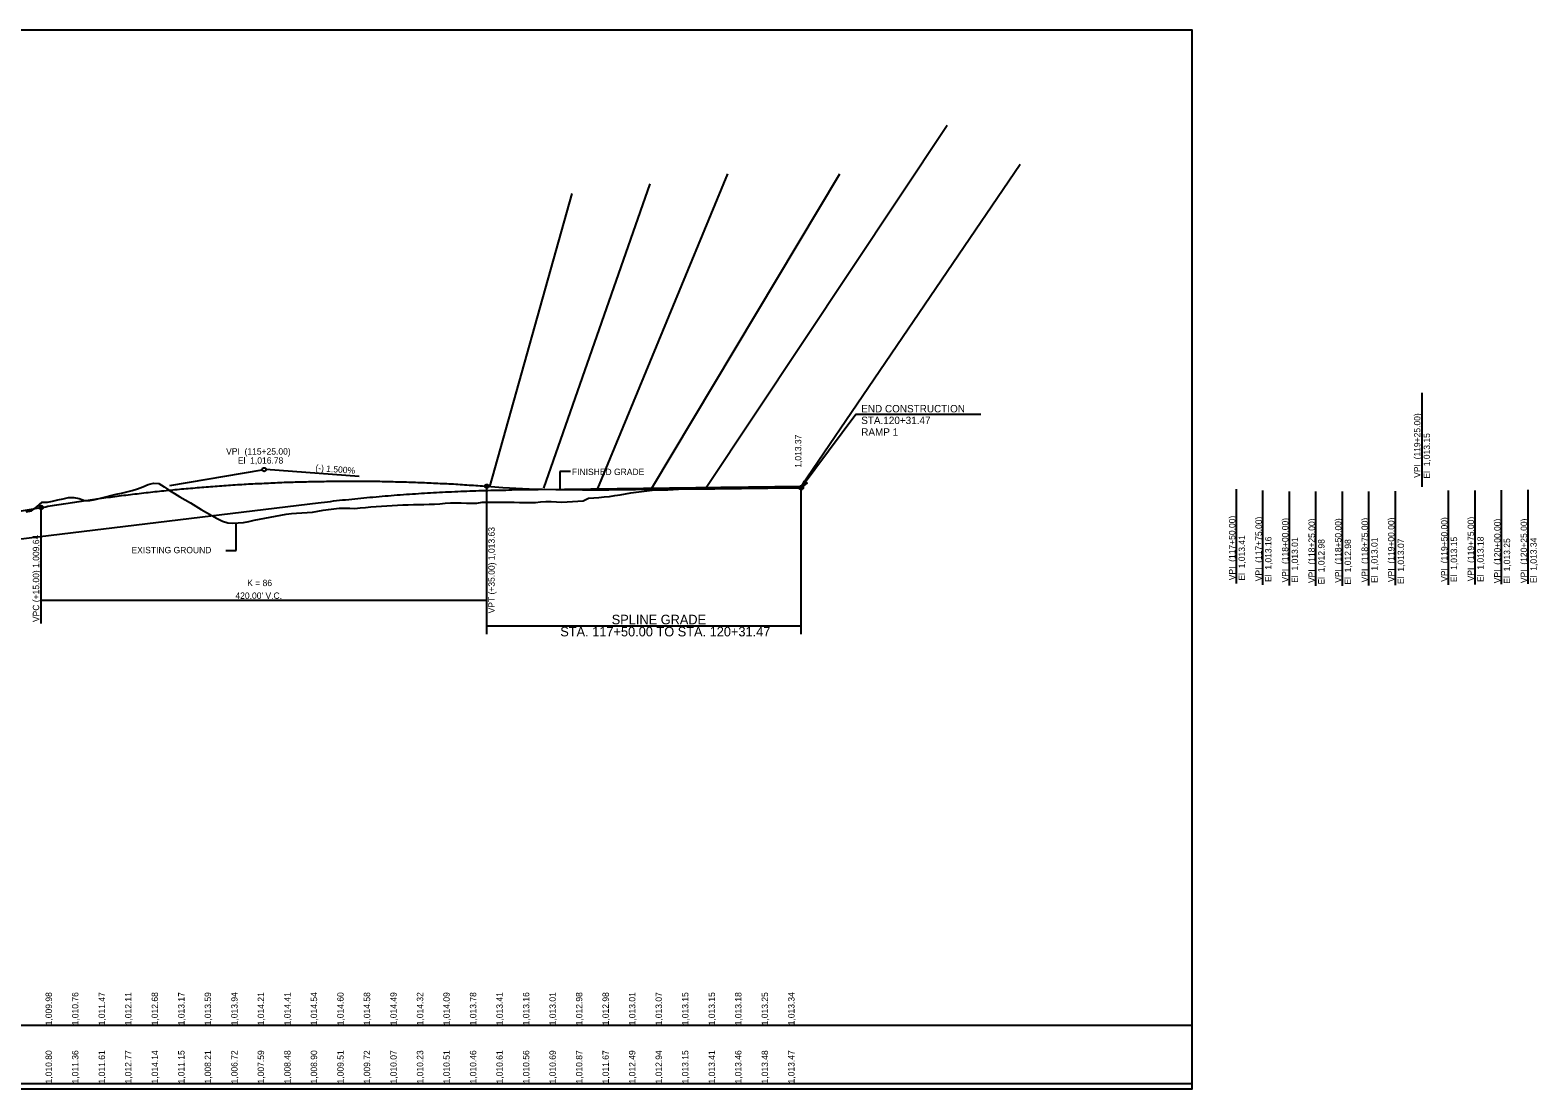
# Model space of a CAD drawing. Extents: x 16972094 to 16980746, y 12563782 to 12565536.
# Drawn here: x 16979324 to 16980746, y 12564538 to 12565536 of the extents above; entities that cross this region are included whole.
import ezdxf

# ---------------------------------------------------------------- set-up
doc = ezdxf.new("R2010")
doc.units = 0
for name, color, linetype in [('Default', 7, 'Continuous'), ('RD_DDB_EX_Tx', 7, 'Continuous'), ('RD_DDB_PR_Tx', 7, 'Continuous'), ('RD_DTM_BkLn1', 7, 'Continuous'), ('RD_EX_BldgChurch', 7, 'Continuous'), ('RD_EX_H2O_Ditch Bottom', 7, 'Continuous'), ('RD_HC_Data', 7, 'Continuous'), ('RD_HY_Area_Dtch', 7, 'Continuous'), ('RD_PD_Supershp_I385', 7, 'Continuous'), ('RD_PD_Supershp_Ramp_7', 7, 'Continuous'), ('RD_SHT_Typical', 7, 'Continuous'), ('RD_Sketch2', 7, 'Continuous'), ('RD_Sketch3', 7, 'Continuous'), ('RD_TX_RoadID', 7, 'Continuous'), ('S_HydraCrossSection', 7, 'Continuous')]:
    doc.layers.add(name, color=color, linetype=linetype)

msp = doc.modelspace()

# ---------------------------------------------------------------- linework, layer by layer
at = {"layer": 'Default'}
msp.add_lwpolyline([(16978919.9, 12564537.8), (16980419.9, 12564537.8), (16980419.9, 12565536), (16978919.9, 12565536)], close=True, dxfattribs=at)
at = {"layer": 'RD_DDB_EX_Tx'}
for p, q in [((16979518.5, 12565045.3), (16979518.5, 12565071.4)), ((16979508.8, 12565045.3), (16979518.5, 12565045.3))]:
    msp.add_line(p, q, dxfattribs=at)
at = {"layer": 'RD_DDB_PR_Tx'}
for p, q in [((16979823.7, 12565119.8), (16979823.7, 12565102.3)), ((16979833.6, 12565119.8), (16979823.7, 12565119.8))]:
    msp.add_line(p, q, dxfattribs=at)
at = {"layer": 'RD_DTM_BkLn1'}
for p, q in [((16978919.9, 12564597.8), (16980419.9, 12564597.8)), ((16978919.9, 12564542.8), (16980419.9, 12564542.8))]:
    msp.add_line(p, q, dxfattribs=at)
at = {"layer": 'RD_EX_BldgChurch'}
for points in [[(16979320.6, 12565081.9), (16979325.6, 12565082.8), (16979330.6, 12565086.4), (16979335.6, 12565090.9), (16979340.6, 12565090.9), (16979345.6, 12565091.9), (16979350.6, 12565093), (16979355.6, 12565094.2), (16979360.6, 12565095.3), (16979365.6, 12565095.5), (16979370.6, 12565094.5), (16979375.6, 12565092.6), (16979380.6, 12565092.6), (16979385.6, 12565093.4), (16979390.6, 12565094.7), (16979395.6, 12565096), (16979400.6, 12565097.2), (16979405.6, 12565098.4), (16979410.6, 12565099.5), (16979415.6, 12565100.6), (16979420.6, 12565101.8), (16979425.6, 12565103.5), (16979430.6, 12565105.5), (16979435.6, 12565107.5), (16979440.6, 12565108.8), (16979445.6, 12565108.4), (16979450.6, 12565105.3), (16979455.6, 12565102.1), (16979460.6, 12565099), (16979465.6, 12565096), (16979470.6, 12565093.2), (16979475.6, 12565090.3), (16979480.6, 12565087.2), (16979485.6, 12565083.9)], [(16979485.6, 12565083.9), (16979490.6, 12565081.2), (16979495.6, 12565078.5), (16979500.6, 12565075.7), (16979505.6, 12565073.1), (16979510.6, 12565071.5), (16979515.6, 12565071.3), (16979520.6, 12565071.4), (16979525.6, 12565071.8), (16979530.6, 12565072.8), (16979535.6, 12565073.9), (16979540.6, 12565074.9), (16979545.6, 12565075.9), (16979550.6, 12565076.9), (16979555.6, 12565077.8), (16979560.6, 12565078.7), (16979565.6, 12565079.7), (16979570.6, 12565080.3), (16979575.6, 12565080.6), (16979580.6, 12565080.9), (16979585.6, 12565081.3), (16979590.6, 12565081.6), (16979595.6, 12565082.4), (16979600.6, 12565083.3), (16979605.6, 12565084.1), (16979610.6, 12565084.6), (16979615.6, 12565085.2), (16979620.6, 12565085.4), (16979625.6, 12565085.2), (16979630.6, 12565085), (16979635.6, 12565085.5), (16979640.6, 12565086), (16979645.6, 12565086.5), (16979650.6, 12565087), (16979655.6, 12565087.3), (16979660.6, 12565087.6), (16979665.6, 12565087.9), (16979670.6, 12565088.2), (16979675.6, 12565088.4), (16979680.6, 12565088.5), (16979685.6, 12565088.7), (16979690.6, 12565088.8), (16979695.6, 12565088.9), (16979700.6, 12565089), (16979705.6, 12565089), (16979710.6, 12565089.4), (16979715.6, 12565090), (16979720.6, 12565090.4), (16979725.6, 12565090.3), (16979730.6, 12565090.2), (16979735.6, 12565090.1), (16979740.6, 12565090), (16979745.6, 12565090.1), (16979750.6, 12565090.8), (16979755.6, 12565091.1), (16979760.6, 12565091), (16979765.6, 12565090.9), (16979770.6, 12565090.9), (16979775.6, 12565090.9), (16979780.6, 12565090.8), (16979785.6, 12565090.7), (16979790.6, 12565090.5), (16979795.6, 12565090.6), (16979800.6, 12565090.7), (16979805.6, 12565091.3), (16979810.6, 12565091.7), (16979815.6, 12565091.5), (16979820.6, 12565091.2), (16979825.6, 12565090.8), (16979830.6, 12565091.3), (16979835.6, 12565091.6), (16979840.6, 12565091.9), (16979845.6, 12565092.2), (16979850.6, 12565094.6), (16979855.6, 12565095), (16979860.6, 12565095.3), (16979865.6, 12565095.9), (16979870.6, 12565096.2), (16979875.6, 12565097.1), (16979880.6, 12565098), (16979885.6, 12565098.9), (16979890.6, 12565099.6), (16979895.6, 12565100.4), (16979900.6, 12565100.9), (16979905.6, 12565101.7), (16979910.6, 12565102.2), (16979915.6, 12565102.5), (16979920.6, 12565102.5), (16979925.6, 12565102.6), (16979930.6, 12565103), (16979935.6, 12565103.3), (16979940.6, 12565103.5), (16979945.6, 12565103.5), (16979950.6, 12565103.7), (16979955.6, 12565104.2), (16979960.6, 12565104.1), (16979965.6, 12565104.6), (16979970.6, 12565104.9), (16979975.6, 12565105), (16979980.6, 12565105.1), (16979985.6, 12565105.1)], [(16979985.6, 12565105.1), (16979990.6, 12565105.1), (16979995.6, 12565105.1), (16980000.6, 12565105.1), (16980005.6, 12565105.1), (16980010.6, 12565105.2), (16980015.6, 12565105.2), (16980020.6, 12565105.2), (16980025.6, 12565105.1), (16980030.6, 12565105.1), (16980035.6, 12565105.2), (16980040.6, 12565105.2), (16980045.6, 12565105.1), (16980050.6, 12565105.2), (16980051.3, 12565105.2)]]:
    msp.add_lwpolyline(points, dxfattribs=at)
at = {"layer": 'RD_EX_H2O_Ditch Bottom'}
for p, q in [((16979456.1, 12565106.6), (16979543.1, 12565121.4)), ((16979634.6, 12565115), (16979546.6, 12565121.6))]:
    msp.add_line(p, q, dxfattribs=at)
for centre in [(16979544.9, 12565121.7), (16980051.3, 12565104.6)]:
    msp.add_circle(centre, 1.75, dxfattribs=at)
at = {"layer": 'RD_HC_Data'}
msp.add_line((16979754.9, 12564974.4), (16980051.3, 12564974.4), dxfattribs=at)
at = {"layer": 'RD_HY_Area_Dtch'}
for p, q in [((16979961.5, 12565104.8), (16980188.7, 12565446.3)), ((16980051.3, 12565105.9), (16980257.5, 12565409.6)), ((16979859.4, 12565103.9), (16979982.1, 12565400.4)), ((16979910.4, 12565104.2), (16980087.7, 12565400.4)), ((16979757.6, 12565105.3), (16979835.2, 12565382)), ((16979808.5, 12565104.3), (16979908.7, 12565391.2))]:
    msp.add_line(p, q, dxfattribs=at)
at = {"layer": 'RD_SHT_Typical'}
msp.add_line((16980220.4, 12565173.6), (16980103.8, 12565173.6), dxfattribs=at)
msp.add_lwpolyline([(16980103.8, 12565173.6), (16980102.7, 12565173.6), (16980051.3, 12565104.6)], dxfattribs=at)
msp.add_lwpolyline([(16980053.9, 12565111.1), (16980051.3, 12565104.6), (16980056.8, 12565109)], close=True, dxfattribs=at)
at = {"layer": 'RD_Sketch2'}
for p, q in [((16980636.4, 12565105.3), (16980636.4, 12565194)), ((16979754.9, 12564966.6), (16979754.9, 12565104.2)), ((16980051.3, 12564966.6), (16980051.3, 12565102.9)), ((16980461.4, 12565014.4), (16980461.4, 12565103.1)), ((16980486.4, 12565013.1), (16980486.4, 12565101.8)), ((16980511.4, 12565012.4), (16980511.4, 12565101.1)), ((16980536.4, 12565012.2), (16980536.4, 12565100.9)), ((16980561.4, 12565012.2), (16980561.4, 12565100.9)), ((16980586.4, 12565012.4), (16980586.4, 12565101.1)), ((16980611.4, 12565012.7), (16980611.4, 12565101.4)), ((16980661.4, 12565013.1), (16980661.4, 12565101.8)), ((16980686.4, 12565013.2), (16980686.4, 12565102)), ((16980711.4, 12565013.5), (16980711.4, 12565102.3)), ((16980736.4, 12565014), (16980736.4, 12565102.7)), ((16979334.9, 12564976.7), (16979334.9, 12565084.3)), ((16979334.9, 12564998.5), (16979754.9, 12564998.5))]:
    msp.add_line(p, q, dxfattribs=at)
for centre in [(16979754.9, 12565106), (16979334.9, 12565086)]:
    msp.add_circle(centre, 1.75, dxfattribs=at)
at = {"layer": 'RD_Sketch3'}
for p, q in [((16979778.5, 12565102.5), (16980051.3, 12565105.9)), ((16978882, 12565004.1), (16979596, 12565090.4))]:
    msp.add_line(p, q, dxfattribs=at)
msp.add_open_spline([(16979596, 12565090.4), (16979687.3, 12565101.4), (16979778.5, 12565102.5)], degree=2, dxfattribs=at)
at = {"layer": 'RD_TX_RoadID'}
for p, q in [((16979754.9, 12565106), (16979769.9, 12565104.8)), ((16979769.9, 12565104.8), (16979794.9, 12565103.6)), ((16979794.9, 12565103.6), (16979819.9, 12565102.9)), ((16979819.9, 12565102.9), (16979844.9, 12565102.7)), ((16979844.9, 12565102.7), (16979869.9, 12565102.7)), ((16979869.9, 12565102.7), (16979894.9, 12565102.8)), ((16979894.9, 12565102.8), (16979919.9, 12565103.1)), ((16979919.9, 12565103.1), (16979944.9, 12565103.5)), ((16979944.9, 12565103.5), (16979969.9, 12565103.5)), ((16979969.9, 12565103.5), (16979994.9, 12565103.7)), ((16979994.9, 12565103.7), (16980019.9, 12565104)), ((16980019.9, 12565104), (16980044.9, 12565104.5)), ((16980044.9, 12565104.5), (16980051.3, 12565104.6)), ((16978919.9, 12565015.5), (16979334.9, 12565086))]:
    msp.add_line(p, q, dxfattribs=at)
msp.add_spline([(16979334.9, 12565086), (16979343.3, 12565087.4), (16979351.7, 12565088.8), (16979360.1, 12565090.1), (16979368.5, 12565091.4), (16979376.9, 12565092.6), (16979385.3, 12565093.8), (16979393.7, 12565095), (16979402.1, 12565096.1), (16979410.5, 12565097.2), (16979418.9, 12565098.2), (16979427.3, 12565099.2), (16979435.7, 12565100.2), (16979444.1, 12565101.1), (16979452.5, 12565102), (16979460.9, 12565102.8), (16979469.3, 12565103.6), (16979477.7, 12565104.3), (16979486.1, 12565105), (16979494.5, 12565105.7), (16979502.9, 12565106.3), (16979511.3, 12565106.9), (16979519.7, 12565107.5), (16979528.1, 12565108), (16979536.5, 12565108.4), (16979544.9, 12565108.8), (16979553.3, 12565109.2), (16979561.7, 12565109.6), (16979570.1, 12565109.9), (16979578.5, 12565110.1), (16979586.9, 12565110.3), (16979595.3, 12565110.5), (16979603.7, 12565110.6), (16979612.1, 12565110.7), (16979620.5, 12565110.8), (16979628.9, 12565110.8), (16979637.3, 12565110.7), (16979645.7, 12565110.7), (16979654.1, 12565110.6), (16979662.5, 12565110.4), (16979670.9, 12565110.2), (16979679.3, 12565110), (16979687.7, 12565109.7), (16979696.1, 12565109.4), (16979704.5, 12565109), (16979712.9, 12565108.6), (16979721.3, 12565108.2), (16979729.7, 12565107.7), (16979738.1, 12565107.1), (16979746.5, 12565106.6), (16979754.9, 12565106)], degree=3, dxfattribs=at)

# ---------------------------------------------------------------- texts
at = {"layer": 'RD_DDB_EX_Tx'}
msp.add_text('EXISTING GROUND', height=6, dxfattribs=at).set_placement((16979419.9, 12565042.8))
at = {"layer": 'RD_DDB_PR_Tx'}
msp.add_text('FINISHED GRADE', height=6, dxfattribs=at).set_placement((16979835.1, 12565116.5))
at = {"layer": 'RD_EX_H2O_Ditch Bottom'}
for s, p in [('VPI  (119+25.00)', (16980634.9, 12565113.9)), ('1,013.37', (16980051.3, 12565123.4)), ('El  1,013.15', (16980643.9, 12565113.2)), ('VPI  (117+50.00)', (16980460.4, 12565017.3)), ('VPI  (117+75.00)', (16980485.4, 12565016.4)), ('VPI  (118+00.00)', (16980510.4, 12565015.2)), ('VPI  (118+25.00)', (16980535.4, 12565014.7)), ('VPI  (118+50.00)', (16980560.4, 12565014.9)), ('VPI  (118+75.00)', (16980585.4, 12565015.3)), ('VPI  (119+00.00)', (16980610.4, 12565015.6)), ('VPI  (119+50.00)', (16980660.4, 12565015.9)), ('VPI  (119+75.00)', (16980685.4, 12565016.3)), ('VPI  (120+00.00)', (16980710.4, 12565014.5)), ('VPI  (120+25.00)', (16980735.4, 12565014.6)), ('El  1,013.41', (16980469.5, 12565017)), ('El  1,013.16', (16980494.5, 12565015.7)), ('El  1,013.01', (16980519.5, 12565014.9)), ('El  1,012.98', (16980544.5, 12565013.3)), ('El  1,012.98', (16980569.5, 12565013.2)), ('El  1,013.01', (16980594.5, 12565014.8)), ('El  1,013.07', (16980619.5, 12565013.8)), ('El  1,013.15', (16980669.5, 12565015.5)), ('El  1,013.18', (16980694.5, 12565015.7)), ('El  1,013.25', (16980719.5, 12565014.1)), ('El  1,013.34', (16980744.5, 12565014.7))]:
    msp.add_text(s, height=6, rotation=90, dxfattribs=at).set_placement(p)
for s, p in [('VPI  (115+25.00)', (16979509.1, 12565135.8)), ('El  1,016.78', (16979520.2, 12565127.3))]:
    msp.add_text(s, height=6, dxfattribs=at).set_placement(p)
at = {"layer": 'RD_HC_Data'}
for s, p in [('SPLINE GRADE', (16979872.6, 12564975.8)), ('STA. 117+50.00 TO STA. 120+31.47', (16979824.1, 12564964.4))]:
    msp.add_text(s, height=9, dxfattribs=at).set_placement(p)
at = {"layer": 'RD_PD_Supershp_I385'}
for s, p in [('1,009.98', (16979344.9, 12564597.7)), ('1,010.76', (16979369.9, 12564597.7)), ('1,011.47', (16979394.9, 12564597.7)), ('1,012.11', (16979419.9, 12564597.7)), ('1,012.68', (16979444.9, 12564597.7)), ('1,013.17', (16979469.9, 12564597.7)), ('1,013.59', (16979494.9, 12564597.7)), ('1,013.94', (16979519.9, 12564597.7)), ('1,014.21', (16979544.9, 12564597.7)), ('1,014.41', (16979569.9, 12564597.7)), ('1,014.54', (16979594.9, 12564597.7)), ('1,014.60', (16979619.9, 12564597.7)), ('1,014.58', (16979644.9, 12564597.7)), ('1,014.49', (16979669.9, 12564597.7)), ('1,014.32', (16979694.9, 12564597.7)), ('1,014.09', (16979719.9, 12564597.7)), ('1,013.78', (16979744.9, 12564597.7)), ('1,013.41', (16979769.9, 12564597.7)), ('1,013.16', (16979794.9, 12564597.7)), ('1,013.01', (16979819.9, 12564597.7)), ('1,012.98', (16979844.9, 12564597.7)), ('1,012.98', (16979869.9, 12564597.7)), ('1,013.01', (16979894.9, 12564597.7)), ('1,013.07', (16979919.9, 12564597.7)), ('1,013.15', (16979944.9, 12564597.7)), ('1,013.15', (16979969.9, 12564597.7)), ('1,013.18', (16979994.9, 12564597.7)), ('1,013.25', (16980019.9, 12564597.7)), ('1,013.34', (16980044.9, 12564597.7))]:
    msp.add_text(s, height=6, rotation=90, dxfattribs=at).set_placement(p)
at = {"layer": 'RD_PD_Supershp_Ramp_7'}
for s, p in [('1,010.80', (16979344.9, 12564542.9)), ('1,011.36', (16979369.9, 12564542.9)), ('1,011.61', (16979394.9, 12564542.9)), ('1,012.77', (16979419.9, 12564542.9)), ('1,014.14', (16979444.9, 12564542.9)), ('1,011.15', (16979469.9, 12564542.9)), ('1,008.21', (16979494.9, 12564542.9)), ('1,006.72', (16979519.9, 12564542.9)), ('1,007.59', (16979544.9, 12564542.9)), ('1,008.48', (16979569.9, 12564542.9)), ('1,008.90', (16979594.9, 12564542.9)), ('1,009.51', (16979619.9, 12564542.9)), ('1,009.72', (16979644.9, 12564542.9)), ('1,010.07', (16979669.9, 12564542.9)), ('1,010.23', (16979694.9, 12564542.9)), ('1,010.51', (16979719.9, 12564542.9)), ('1,010.46', (16979744.9, 12564542.9)), ('1,010.61', (16979769.9, 12564542.9)), ('1,010.56', (16979794.9, 12564542.9)), ('1,010.69', (16979819.9, 12564542.9)), ('1,010.87', (16979844.9, 12564542.9)), ('1,011.67', (16979869.9, 12564542.9)), ('1,012.49', (16979894.9, 12564542.9)), ('1,012.94', (16979919.9, 12564542.9)), ('1,013.15', (16979944.9, 12564542.9)), ('1,013.41', (16979969.9, 12564542.9)), ('1,013.46', (16979994.9, 12564542.9)), ('1,013.48', (16980019.9, 12564542.9)), ('1,013.47', (16980044.9, 12564542.9))]:
    msp.add_text(s, height=6, rotation=90, dxfattribs=at).set_placement(p)
at = {"layer": 'RD_SHT_Typical'}
for s, p in [('END CONSTRUCTION', (16980107.8, 12565175.6)), ('STA.120+31.47 ', (16980107.8, 12565164.6)), ('RAMP 1', (16980107.8, 12565153.6))]:
    msp.add_text(s, height=7, dxfattribs=at).set_placement(p)
at = {"layer": 'RD_Sketch2'}
for s, p in [('VPT (+35.00) 1,013.63', (16979762.3, 12564986.1)), ('VPC (+15.00) 1,009.64', (16979332.9, 12564977.9))]:
    msp.add_text(s, height=6, rotation=90, dxfattribs=at).set_placement(p)
for s, p in [('K = 86', (16979529, 12565011.8)), ("420.00' V.C.", (16979517.9, 12564999.8))]:
    msp.add_text(s, height=6, dxfattribs=at).set_placement(p)
at = {"layer": 'S_HydraCrossSection'}
msp.add_text('(-) 1.500%', height=6, rotation=355.7108, dxfattribs=at).set_placement((16979593.1, 12565120.4))

doc.saveas('drawing.dxf')
